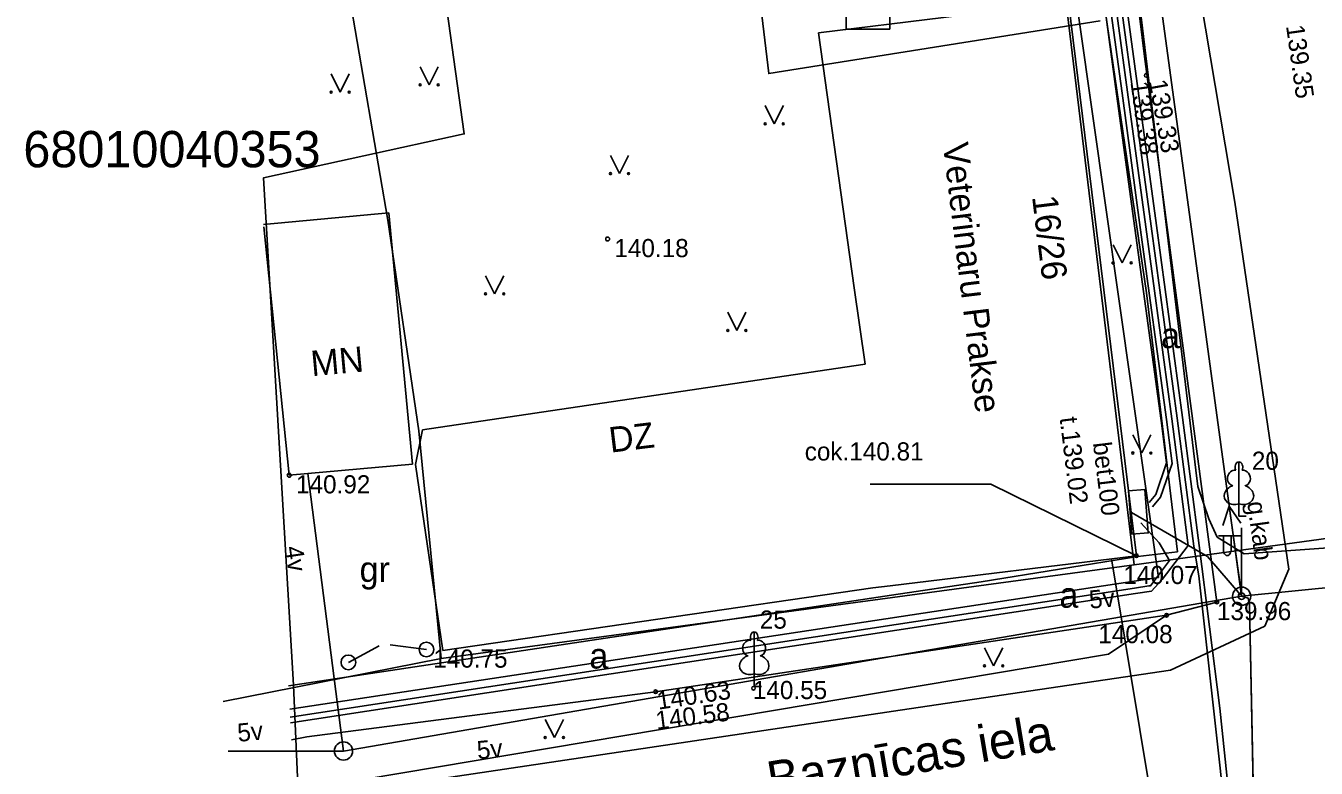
# Model space of a CAD drawing. Extents: x 728710 to 728960, y 272811 to 273475.
# Drawn here: x 728766.5 to 728802.02, y 273212.21 to 273232.66 of the extents above; entities that cross this region are included whole.
import ezdxf

# ---------------------------------------------------------------- set-up
doc = ezdxf.new("R2010")
doc.units = 0
for name, color, linetype in [('GEOD_ELEM_####_TKST_#', 7, 'Continuous'), ('Level 15', 7, 'Continuous'), ('Level 16', 7, 'Continuous'), ('Level 20', 7, 'Continuous'), ('Level 21', 7, 'Continuous'), ('Level 23', 7, 'Continuous'), ('Level 26', 7, 'Continuous'), ('Level 3', 7, 'Continuous'), ('Level 4', 7, 'Continuous'), ('Level 42', 7, 'Continuous'), ('Level 43', 7, 'Continuous'), ('Level 45', 7, 'Continuous'), ('Level 48', 7, 'Continuous'), ('Level 50', 7, 'Continuous'), ('Level 53', 7, 'Continuous'), ('Level 54', 7, 'Continuous'), ('Level 57', 7, 'Continuous'), ('Level 58', 7, 'Continuous'), ('Level 59', 7, 'Continuous'), ('Level 60', 7, 'Continuous'), ('Level 62', 7, 'Continuous'), ('Level 9', 7, 'Continuous'), ('RAMI_UZMR_####_####_#', 7, 'Continuous'), ('RELJ_ELEM_####_####_#', 7, 'Continuous'), ('RELJ_NOGA_####_####_#', 7, 'Continuous'), ('ROBZ_ELEM_####_####_#', 7, 'Continuous'), ('ROBZ_KADS_####_TKST_#', 7, 'Continuous'), ('ROBZ_UZMR_####_####_#', 7, 'Continuous'), ('TERT_KONT_####_####_#', 7, 'Continuous')]:
    doc.layers.add(name, color=color, linetype=linetype)

msp = doc.modelspace()

# ---------------------------------------------------------------- linework, layer by layer
at = {"layer": 'GEOD_ELEM_####_TKST_#'}
msp.add_lwpolyline([(728801.008, 273204.855), (728800.415, 273204.912), (728800.181, 273216.709), (728800.141, 273216.891)], dxfattribs=at)
at = {"layer": 'Level 15'}
for points in [[(728789.081, 273233.019), (728790.282, 273233.019), (728790.281, 273232.568), (728789.08, 273232.568)], [(728796.943, 273218.654), (728796.854, 273219.851), (728797.303, 273219.884), (728797.392, 273218.688)]]:
    msp.add_lwpolyline(points, close=True, dxfattribs=at)
for centre in [(728799.963, 273216.945), (728775.244, 273212.681)]:
    msp.add_circle(centre, 0.25, dxfattribs=at)
at = {"layer": 'Level 16'}
for points in [[(728790.477, 273216.013), (728797.041, 273217.017), (728797.486, 273217.085), (728797.777, 273217.408), (728798.493, 273218.343), (728798.042, 273221.829), (728797.325, 273227.119), (728796.821, 273230.824), (728796.286, 273234.768)], [(728797.417, 273219.529), (728797.598, 273219.748), (728797.897, 273220.614), (728797.745, 273221.789), (728797.027, 273227.078), (728796.524, 273230.784), (728795.987, 273234.738)], [(728797.509, 273219.41), (728797.731, 273219.674), (728798.049, 273220.599), (728797.893, 273221.809), (728797.175, 273227.098), (728796.672, 273230.804), (728796.136, 273234.753)], [(728798.647, 273218.321), (728798.191, 273221.849), (728797.473, 273227.139), (728796.97, 273230.845), (728796.436, 273234.783)], [(728798.795, 273218.34), (728798.339, 273221.868), (728797.621, 273227.159), (728797.118, 273230.865), (728796.584, 273234.798)], [(728796.932, 273219.249), (728799.02, 273218.037), (728799.93, 273216.986)], [(728790.454, 273216.162), (728797.018, 273217.166), (728797.409, 273217.226), (728797.458, 273217.232), (728797.98, 273217.928), (728797.692, 273218.418), (728797.186, 273218.968)], [(728798.647, 273218.321), (728798.79, 273217.505), (728799.373, 273212.209), (728799.822, 273207.956), (728800.089, 273204.952), (728800.017, 273204.781), (728799.85, 273204.575), (728799.252, 273204.449)], [(728799.366, 273204.415), (728799.867, 273204.517), (728800.041, 273204.634), (728800.179, 273204.73), (728800.235, 273205.009), (728800.072, 273207.092), (728799.365, 273213.863), (728798.795, 273218.34)], [(728773.779, 273213.612), (728785.353, 273215.382), (728790.454, 273216.162)], [(728773.787, 273213.461), (728785.376, 273215.233), (728790.477, 273216.013)]]:
    msp.add_lwpolyline(points, dxfattribs=at)
at = {"layer": 'Level 20'}
for q in [(728799.445, 273218.893), (728799.941, 273218.96), (728799.929, 273217.193)]:
    msp.add_line((728799.625, 273219.422), q, dxfattribs=at)
at = {"layer": 'Level 21'}
for p, q in [((728796.674, 273241.078), (728799.963, 273216.945)), ((728774.266, 273220.324), (728775.244, 273212.681)), ((728799.963, 273216.945), (728822.971, 273219.263)), ((728799.963, 273216.945), (728790.584, 273215.327)), ((728790.584, 273215.327), (728775.244, 273212.681)), ((728775.244, 273212.681), (728772.073, 273212.681))]:
    msp.add_line(p, q, dxfattribs=at)
at = {"layer": 'Level 23'}
msp.add_lwpolyline([(728797.551, 273210.954), (728796.382, 273217.977)], dxfattribs=at)
at = {"layer": 'Level 26'}
for p, q in [((728799.963, 273216.945), (728799.963, 273218.828)), ((728799.963, 273218.612), (728799.328, 273218.607)), ((728799.463, 273218.608), (728799.463, 273218.216)), ((728799.673, 273218.61), (728799.673, 273218.216))]:
    msp.add_line(p, q, dxfattribs=at)
msp.add_circle((728799.963, 273216.945), 0.09, dxfattribs=at)
msp.add_ellipse((728799.568, 273218.216), major_axis=(0, 0.151), ratio=0.695971, start_param=1.570796, end_param=4.712389, dxfattribs=at)
at = {"layer": 'Level 3'}
for p, q in [((728795.197, 273233.307), (728788.317, 273232.464)), ((728797.066, 273218.061), (728795.197, 273233.307)), ((728788.317, 273232.464), (728789.304, 273225.44)), ((728776.493, 273227.509), (728773.045, 273227.184)), ((728777.142, 273220.586), (728776.493, 273227.509)), ((728773.049, 273227.116), (728773.752, 273220.277)), ((728789.304, 273225.44), (728789.599, 273223.337)), ((728777.42, 273221.527), (728789.534, 273223.327)), ((728789.534, 273223.327), (728789.599, 273223.337)), ((728777.228, 273220.569), (728777.42, 273221.527)), ((728773.752, 273220.277), (728777.142, 273220.586)), ((728777.976, 273215.445), (728777.228, 273220.569)), ((728797.066, 273218.061), (728790.287, 273217.23)), ((728789.809, 273217.171), (728777.976, 273215.445)), ((728790.287, 273217.23), (728789.809, 273217.171))]:
    msp.add_line(p, q, dxfattribs=at)
at = {"layer": 'Level 4'}
for p, q in [((728797.287, 273231.807), (728793.815, 273260.182)), ((728795.97, 273234.736), (728797.349, 273225.3)), ((728799.284, 273216.785), (728797.287, 273231.807)), ((728797.349, 273225.3), (728798.201, 273218.164)), ((728776.829, 273220.535), (728776.829, 273220.536)), ((728798.201, 273218.164), (728797.107, 273218.034)), ((728792.794, 273217.34), (728797.107, 273218.034)), ((728797.107, 273218.034), (728797.107, 273218.034)), ((728792.794, 273217.34), (728790.327, 273216.97)), ((728790.327, 273216.97), (728773.732, 273214.477)), ((728797.897, 273216.42), (728799.284, 273216.785)), ((728773.812, 273212.989), (728774.233, 273213.073))]:
    msp.add_line(p, q, dxfattribs=at)
for points in [[(728795.499, 273237.956), (728786.359, 273236.325), (728786.949, 273231.342), (728796.072, 273232.795)], [(728797.897, 273216.42), (728783.834, 273214.312), (728774.233, 273213.073)]]:
    msp.add_lwpolyline(points, dxfattribs=at)
at = {"layer": 'Level 42'}
for points in [[(728790.816, 273213.839), (728798.005, 273214.912), (728800.599, 273216.119), (728801.262, 273217.688), (728799.779, 273227.802), (728798.57, 273234.996)], [(728796.953, 273234.834), (728797.171, 273233.12), (728798.705, 273220.412), (728798.759, 273219.965), (728799.063, 273219.076), (728799.29, 273218.573), (728800.035, 273218.111), (728802.6, 273218.3), (728805.991, 273218.55), (728811.368, 273219.028), (728821.256, 273220.241)], [(728773.902, 273211.333), (728775.244, 273211.516), (728790.816, 273213.839)]]:
    msp.add_lwpolyline(points, dxfattribs=at)
at = {"layer": 'Level 43'}
for p, q in [((728775.38, 273215.122), (728776.224, 273215.582)), ((728777.528, 273215.477), (728776.526, 273215.609))]:
    msp.add_line(p, q, dxfattribs=at)
for centre in [(728777.528, 273215.477), (728775.38, 273215.122)]:
    msp.add_circle(centre, 0.202, dxfattribs=at)
at = {"layer": 'Level 45'}
msp.add_lwpolyline([(728774.752, 273211.72), (728796.297, 273215.351), (728797.897, 273216.42)], dxfattribs=at)
at = {"layer": 'Level 48'}
for centre, radius in [((728797.337, 273231.288), 0.05), ((728782.514, 273226.784), 0.0534), ((728773.752, 273220.277), 0.0534), ((728797.068, 273218.06), 0.05), ((728799.284, 273216.785), 0.05), ((728797.897, 273216.42), 0.05), ((728783.834, 273214.312), 0.05), ((728786.529, 273214.409), 0.05)]:
    msp.add_circle(centre, radius, dxfattribs=at)
at = {"layer": 'Level 9'}
for points in [[(728789.894, 273220.031), (728789.741, 273220.031)], [(728797.066, 273218.061), (728793.064, 273220.031), (728789.894, 273220.031)]]:
    msp.add_lwpolyline(points, dxfattribs=at)
at = {"layer": 'RAMI_UZMR_####_####_#'}
msp.add_lwpolyline([(728776.746, 273299.712), (728774.767, 273288.109), (728769.195, 273286.654), (728770.672, 273271.11), (728776.42, 273245.146), (728778.568, 273229.68), (728773.046, 273228.469), (728773.87, 273214.498), (728774.426, 273201.627), (728776.99, 273195.753), (728795.127, 273200.451), (728799.264, 273172.386), (728794.758, 273166.22), (728789.327, 273163.194), (728788.892, 273161.497), (728790.999, 273149.932)], dxfattribs=at)
at = {"layer": 'RELJ_ELEM_####_####_#'}
msp.add_lwpolyline([(728799.963, 273216.945), (728800.141, 273216.891), (728800.181, 273216.709), (728800.371, 273207.399), (728800.415, 273204.912), (728800.619, 273204.837), (728801.02, 273204.847)], dxfattribs=at)
at = {"layer": 'ROBZ_ELEM_####_####_#'}
for points in [[(728797.679, 273217.456), (728777.701, 273357.893)], [(728797.679, 273217.456), (728773.766, 273213.837)]]:
    msp.add_lwpolyline(points, dxfattribs=at)
at = {"layer": 'ROBZ_UZMR_####_####_#'}
for p, q in [((728774.418, 273239.286), (728776.461, 273227.298)), ((728797.009, 273217.805), (728795.166, 273233.048)), ((728776.461, 273227.298), (728777.319, 273221.497)), ((728777.319, 273221.497), (728777.936, 273215.232)), ((728797.009, 273217.805), (728809.201, 273219.485)), ((728777.936, 273215.232), (728797.009, 273217.805)), ((728771.936, 273214.046), (728777.936, 273215.232))]:
    msp.add_line(p, q, dxfattribs=at)
at = {"layer": 'TERT_KONT_####_####_#'}
for p, q in [((728774.903, 273231.33), (728775.153, 273230.83)), ((728775.153, 273230.83), (728775.403, 273231.33)), ((728777.354, 273231.53), (728777.604, 273231.03)), ((728777.604, 273231.03), (728777.854, 273231.53)), ((728786.85, 273230.457), (728787.1, 273229.957)), ((728787.1, 273229.957), (728787.35, 273230.457)), ((728782.591, 273229.084), (728782.841, 273228.584)), ((728782.841, 273228.584), (728783.091, 273229.084)), ((728796.424, 273226.624), (728796.674, 273226.124)), ((728796.674, 273226.124), (728796.924, 273226.624)), ((728779.154, 273225.773), (728779.404, 273225.273)), ((728779.404, 273225.273), (728779.654, 273225.773)), ((728785.821, 273224.765), (728786.071, 273224.265)), ((728786.071, 273224.265), (728786.321, 273224.765)), ((728796.967, 273221.39), (728797.217, 273220.89)), ((728797.217, 273220.89), (728797.467, 273221.39)), ((728799.889, 273219.492), (728799.889, 273219.145)), ((728799.889, 273219.145), (728800.089, 273219.145)), ((728792.888, 273215.526), (728793.138, 273215.026)), ((728793.138, 273215.026), (728793.388, 273215.526)), ((728786.548, 273214.809), (728786.548, 273214.462)), ((728786.548, 273214.462), (728786.748, 273214.462)), ((728780.798, 273213.552), (728781.048, 273213.052)), ((728781.048, 273213.052), (728781.298, 273213.552))]:
    msp.add_line(p, q, dxfattribs=at)
for points in [[(728799.889, 273220.645), (728799.889, 273219.492)], [(728799.979, 273220.413), (728799.978, 273220.414)], [(728786.548, 273215.962), (728786.548, 273214.809)], [(728786.638, 273215.729), (728786.637, 273215.73)]]:
    msp.add_lwpolyline(points, dxfattribs=at)
for centre, radius in [((728774.903, 273230.829), 0.028), ((728775.403, 273230.829), 0.0263), ((728777.353, 273231.029), 0.028), ((728777.853, 273231.029), 0.0263), ((728786.849, 273229.957), 0.028), ((728787.349, 273229.957), 0.0263), ((728782.591, 273228.584), 0.028), ((728783.091, 273228.584), 0.0263), ((728796.424, 273226.124), 0.028), ((728796.924, 273226.124), 0.0263), ((728779.154, 273225.273), 0.028), ((728779.654, 273225.273), 0.0263), ((728785.821, 273224.264), 0.028), ((728786.321, 273224.264), 0.0263), ((728796.967, 273220.889), 0.028), ((728797.467, 273220.889), 0.0263), ((728792.887, 273215.025), 0.028), ((728793.387, 273215.025), 0.0263), ((728780.798, 273213.052), 0.028), ((728781.298, 273213.052), 0.0263)]:
    msp.add_circle(centre, radius, dxfattribs=at)
for centre, major_axis, ratio, start_param, end_param in [((728799.889, 273220.495), (0, -0.15), 0.707107, 3.14537, 5.287485), ((728799.889, 273220.495), (0, -0.15), 0.707107, 0.995701, 3.137816), ((728799.761, 273220.2), (-0.039, -0.212), 0.861323, 3.141593, 6.283185), ((728800.017, 273220.2), (0.039, -0.212), 0.861323, 0, 3.141593), ((728799.799, 273219.738), (0.307, 0.095), 0.814445, 1.570796, 4.752015), ((728799.979, 273219.738), (-0.307, 0.095), 0.814445, 1.531171, 4.712389), ((728786.549, 273215.812), (0, -0.15), 0.707107, 3.14537, 5.287485), ((728786.548, 273215.812), (0, -0.15), 0.707107, 0.995701, 3.137816), ((728786.42, 273215.517), (-0.039, -0.212), 0.861323, 3.141593, 6.283185), ((728786.676, 273215.517), (0.039, -0.212), 0.861323, 0, 3.141593), ((728786.459, 273215.055), (0.307, 0.095), 0.814445, 1.570796, 4.752015), ((728786.638, 273215.055), (-0.307, 0.095), 0.814445, 1.531171, 4.712389)]:
    msp.add_ellipse(centre, major_axis=major_axis, ratio=ratio, start_param=start_param, end_param=end_param, dxfattribs=at)

# ---------------------------------------------------------------- texts
at = {"layer": 'Level 50'}
msp.add_text('cok.140.81', height=0.5, dxfattribs=at).set_placement((728787.939, 273220.683))
at = {"layer": 'Level 53'}
for s, rotation, p in [('g.kab', 277.761, (728800.115, 273219.527)), ('4v', 278.342, (728773.63, 273218.294)), ('5v', 5.341, (728795.788, 273216.6)), ('5v', 5.341, (728772.346, 273212.933)), ('5v', 5.341, (728778.94, 273212.452))]:
    msp.add_text(s, height=0.5, rotation=rotation, dxfattribs=at).set_placement(p)
at = {"layer": 'Level 54'}
msp.add_text('Baznīcas iela', height=1, rotation=9.6084, dxfattribs=at).set_placement((728786.999, 273211.385))
at = {"layer": 'Level 57'}
for s, rotation, p in [('139.35', 277.9552, (728801.185, 273232.65)), ('139.38', 278.0143, (728796.903, 273231.094)), ('139.33', 280.1795, (728797.406, 273231.133)), ('140.63', 8.5963, (728783.909, 273213.818)), ('140.58', 7.1636, (728783.867, 273213.268))]:
    msp.add_text(s, height=0.5, rotation=rotation, dxfattribs=at).set_placement(p)
for s, p in [(' 140.18', (728782.514, 273226.284)), (' 140.92', (728773.752, 273219.777)), (' 140.07', (728796.523, 273217.28)), ('139.96', (728799.284, 273216.285)), ('140.08', (728796.019, 273215.651)), (' 140.75', (728777.528, 273214.977)), ('140.55', (728786.511, 273214.111))]:
    msp.add_text(s, height=0.5, dxfattribs=at).set_placement(p)
at = {"layer": 'Level 58'}
for s, p in [('a', (728797.746, 273223.777)), ('gr', (728775.688, 273217.335)), ('a', (728794.948, 273216.628)), ('a', (728782.01, 273214.953))]:
    msp.add_text(s, height=0.7, dxfattribs=at).set_placement(p)
at = {"layer": 'Level 59'}
for s, rotation, p in [('Veterinaru Prakse', 276.989, (728791.738, 273229.397)), ('MN', 5.2081, (728774.375, 273223.003)), ('DZ', 6.989, (728782.596, 273220.897))]:
    msp.add_text(s, height=0.7, rotation=rotation, dxfattribs=at).set_placement(p)
at = {"layer": 'Level 60'}
for s, p in [('t.139.02', (728794.954, 273221.855)), ('bet100', (728795.869, 273221.165))]:
    msp.add_text(s, height=0.5, rotation=276.989, dxfattribs=at).set_placement(p)
at = {"layer": 'Level 62'}
msp.add_text('16/26', height=0.7, rotation=276.989, dxfattribs=at).set_placement((728794.194, 273227.949))
at = {"layer": 'RELJ_NOGA_####_####_#'}
for s, p in [('20', (728800.245, 273220.426)), ('25', (728786.703, 273216.051))]:
    msp.add_text(s, height=0.5, dxfattribs=at).set_placement(p)
at = {"layer": 'ROBZ_KADS_####_TKST_#'}
msp.add_text('68010040353', height=1, dxfattribs=at).set_placement((728766.433, 273228.759))

doc.saveas('drawing.dxf')
